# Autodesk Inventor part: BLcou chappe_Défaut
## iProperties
Shininess: 64.0
Length Units: 11269
Angle Units: 11279
Time Units: 11290
Mass Units: 11283
Length Display Precision: 3
Angle Display Precision: 2
Compacted: True
Part Number: BLcou chappe_Défaut
Document SubType Name: Modeling
Created: 2006-11
Material: Par défaut
Designer: profs_sti
Density: 0.0
Volumn: 0.0
Area: 0.0
PropertySet Name: Model Information
Control State: 0
Master: False
Checked Out: False
Author: profs_sti
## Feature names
1. Base1
